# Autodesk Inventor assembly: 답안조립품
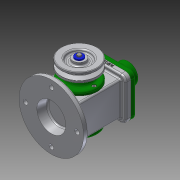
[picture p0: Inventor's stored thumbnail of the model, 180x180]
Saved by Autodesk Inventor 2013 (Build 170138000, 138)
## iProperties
Created: 2018-10
Part Number: 답안조립품
Document SubType Name: Assembly
Designer: Administrator
Author: Administrator
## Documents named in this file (18)
- C:\Users\Administrator\Desktop\481007V1068\답안조립품.iam
- C:\Users\Administrator\Desktop\481007V1068\본체.ipt
- C:\Users\Administrator\Desktop\481007V1068\E-링.ipt
- C:\Users\Administrator\Desktop\481007V1068\V-벨트풀리.ipt
- C:\Users\Administrator\Desktop\481007V1068\덮개.ipt
- C:\Users\Administrator\Desktop\481007V1068\뒤커버.ipt
- C:\Users\Administrator\Desktop\481007V1068\링크.ipt
- C:\Users\Administrator\Desktop\481007V1068\베어링 17 x 40 x 12.ipt
- C:\Users\Administrator\Desktop\481007V1068\볼트 M4 x 8.ipt
- C:\Users\Administrator\Desktop\481007V1068\볼트 M4 x 10.ipt
- C:\Users\Administrator\Desktop\481007V1068\슬라이더.ipt
- C:\Users\Administrator\Desktop\481007V1068\앞커버.ipt
- C:\Users\Administrator\Desktop\481007V1068\오일 실 17 30 8.ipt
- C:\Users\Administrator\Desktop\481007V1068\와셔 4x16.ipt
- C:\Users\Administrator\Desktop\481007V1068\클레비스 핀 6 x 22.ipt
- 클레비스 핀 6 x 22.ipt
- C:\Users\Administrator\Desktop\481007V1068\키 4 x 4 x 12.ipt
- C:\Users\Administrator\Desktop\481007V1068\편심축.ipt
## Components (2 placed, 2 different names)
1. E-링:1
2. V-벨트풀리:1 — 플러쉬:2
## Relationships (1: Flush 1)
- 플러쉬:2 [Flush]: V-벨트풀리:1
